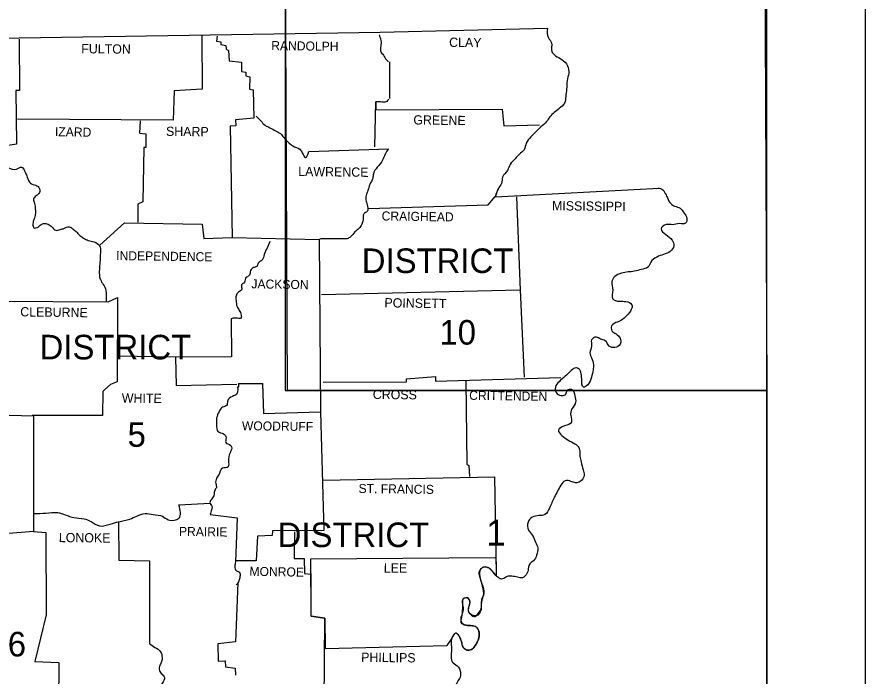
# Model space of a CAD drawing. Extents: x -492261 to -432772, y 1441225 to 1452922.
# Drawn here: x -457159 to -456748.3, y 1452098.1 to 1452417.2 of the extents above; entities that cross this region are included whole.
import ezdxf

# ---------------------------------------------------------------- set-up
doc = ezdxf.new("R2010")
doc.units = 0
for name, color, linetype in [('Default', 7, 'Continuous'), ('R_Border', 7, 'Continuous'), ('R_No Plot', 7, 'Continuous')]:
    doc.layers.add(name, color=color, linetype=linetype)

msp = doc.modelspace()

# ---------------------------------------------------------------- linework, layer by layer
at = {"layer": 'Default'}
for p, q in [((-456927.17, 1452330.17), (-456925.92, 1452334.04)), ((-456926.86, 1452331.43), (-456925.61, 1452334.46)), ((-457051.63, 1452239.76), (-457039.96, 1452239.76)), ((-457016.65, 1452154.87), (-456927.59, 1452155.5)), ((-457016.55, 1452140.93), (-457016.65, 1452154.87)), ((-457016.45, 1452126.99), (-457016.55, 1452140.93)), ((-456943.88, 1452124.9), (-456943.3, 1452128.3)), ((-457016.45, 1452126.99), (-457009.87, 1452126.05)), ((-457009.87, 1452126.05), (-457009.66, 1452111.33)), ((-457009.66, 1452111.33), (-456950.77, 1452112.79))]:
    msp.add_line(p, q, dxfattribs=at)
for points in [[(-457474.92, 1452406.92), (-457306.08, 1452406.81), (-457157.92, 1452407.12), (-456983.14, 1452409.84), (-456902.11, 1452411.72)], [(-457069.49, 1452408.06), (-457069.28, 1452382.17), (-457082.85, 1452381.44), (-457083.27, 1452367.24), (-457158.76, 1452367.66)], [(-457061.97, 1452407.96), (-457062.28, 1452405.45), (-457060.19, 1452405.14), (-457060.3, 1452403.89), (-457057.9, 1452403.37), (-457057.69, 1452401.69), (-457056.54, 1452400.96), (-457056.23, 1452395.95), (-457050.28, 1452395.33), (-457050.28, 1452390.84), (-457048.08, 1452390.52), (-457048.08, 1452388.75), (-457046.2, 1452388.23), (-457046.31, 1452382.17), (-457044.64, 1452381.86), (-457044.22, 1452368.18), (-457053.09, 1452367.34), (-457052.99, 1452364.42), (-457055.7, 1452364.32), (-457054.76, 1452310.44), (-457012.69, 1452309.5), (-457011.96, 1452225.77), (-457039.42, 1452225.03), (-457039.96, 1452239.76)], [(-457157.92, 1452406.5), (-457157.71, 1452381.65), (-457159.49, 1452381.54), (-457159.18, 1452355.55), (-457166.49, 1452354.5), (-457165.86, 1452347.51), (-457163.35, 1452344.27), (-457163.56, 1452336.02), (-457177.76, 1452335.5), (-457178.28, 1452322.76), (-457191.23, 1452322.34), (-457191.86, 1452306.89), (-457191.13, 1452305.64), (-457190.81, 1452281), (-457168.47, 1452279.54), (-457168.78, 1452224.51), (-457151.03, 1452223.99), (-457151.03, 1452168.03), (-457165.02, 1452166.98), (-457166.07, 1452154.66), (-457189.56, 1452154.56)], [(-456978.54, 1452395.43), (-456978.54, 1452377.79)], [(-456985.64, 1452354.29), (-456985.12, 1452376.11), (-456985.12, 1452372.25), (-456924.04, 1452372.56), (-456923.21, 1452364.42), (-456905.98, 1452365.05)], [(-457099.35, 1452366.93), (-457099.56, 1452360.87), (-457096.63, 1452360.66), (-457096.53, 1452353.98), (-457097.57, 1452353.98), (-457097.99, 1452327.67), (-457100.39, 1452326.62), (-457100.39, 1452317.85)], [(-457017.59, 1452352), (-456978.86, 1452353.35)], [(-456927.17, 1452330.17), (-456847.92, 1452334.25)], [(-456988.78, 1452324.43), (-456930.83, 1452326.31), (-456927.38, 1452330.28)], [(-456917.15, 1452330.07), (-456915.38, 1452284.86), (-456913.29, 1452242.78)], [(-457118.77, 1452306.68), (-457106.87, 1452317.44), (-457069.28, 1452316.91), (-457068.55, 1452309.92), (-457054.87, 1452310.44)], [(-456999.01, 1452309.71), (-457011.75, 1452309.71), (-457012.69, 1452309.5)], [(-456915.38, 1452284.86), (-457011.54, 1452282.67)], [(-457168.47, 1452279.54), (-457114.8, 1452279.22), (-457110.21, 1452281.42), (-457110.52, 1452240.59), (-457113.65, 1452239.23), (-457116.47, 1452236.83), (-457117.41, 1452235.89), (-457117.52, 1452224.2), (-457151.66, 1452224.2)], [(-457055.29, 1452270.97), (-457055.08, 1452252.6), (-457082.23, 1452252.49), (-457110.1, 1452253.02)], [(-457082.23, 1452252.49), (-457081.81, 1452238.82), (-457052.47, 1452239.34)], [(-457010.7, 1452240.38), (-456970.4, 1452240.59), (-456970.3, 1452242.05), (-456956.3, 1452243.1), (-456956.3, 1452240.9), (-456895.54, 1452242.58)], [(-457051.63, 1452239.76), (-457051.63, 1452237.98), (-457052.15, 1452237.88)], [(-456941.69, 1452240.9), (-456941.16, 1452200.71), (-456940.23, 1452200.08), (-456939.91, 1452194.65)], [(-456941.69, 1452240.9), (-456941.16, 1452200.71), (-456940.23, 1452200.08), (-456939.91, 1452194.65)], [(-456941.69, 1452240.9), (-456941.16, 1452200.71), (-456940.23, 1452200.08), (-456939.91, 1452194.65)], [(-456941.69, 1452240.9), (-456941.16, 1452200.71), (-456940.23, 1452200.08), (-456939.91, 1452194.65)], [(-456941.69, 1452240.9), (-456941.16, 1452200.71), (-456940.23, 1452200.08), (-456939.91, 1452194.65)], [(-457011.96, 1452225.77), (-457010.39, 1452168.55), (-457035.24, 1452168.44), (-457035.34, 1452166.15), (-457042.55, 1452165.73), (-457043.18, 1452153.83), (-457053.08, 1452153.83)], [(-457010.7, 1452192.88), (-456927.8, 1452194.55)], [(-456927.8, 1452194.55), (-456926.96, 1452148.82)], [(-456927.8, 1452194.55), (-456926.96, 1452148.82)], [(-456927.8, 1452194.55), (-456926.96, 1452148.82)], [(-456927.8, 1452194.55), (-456926.96, 1452148.82)], [(-456927.8, 1452194.55), (-456926.96, 1452148.82)], [(-456927.8, 1452194.55), (-456926.96, 1452148.82)], [(-456927.8, 1452194.55), (-456926.96, 1452148.82)], [(-456927.8, 1452194.55), (-456926.96, 1452148.82)], [(-457080.55, 1452180.97), (-457065.41, 1452181.7)], [(-457109.79, 1452172.83), (-457109.58, 1452154.14), (-457094.86, 1452153.83), (-457094.75, 1452113.73)], [(-457065.41, 1452176.28), (-457052.36, 1452174.6), (-457053.09, 1452153.31)], [(-457151.03, 1452168.03), (-457144.98, 1452167.61), (-457144.87, 1452127.72), (-457150.3, 1452105.07), (-457138.71, 1452104.55), (-457138.82, 1452084.59)], [(-457024.59, 1452167.92), (-457024.69, 1452154.98), (-457019.89, 1452154.98), (-457019.68, 1452147.77), (-457016.65, 1452147.46)], [(-457010.7, 1452062.36), (-457002.56, 1452062.89), (-457002.66, 1452084.08), (-457010.29, 1452084.6), (-457009.87, 1452126.05), (-457016.45, 1452126.99), (-457016.65, 1452154.87), (-456927.59, 1452155.5)], [(-456927.59, 1452155.5), (-456927.09, 1452155.51), (-456926.96, 1452148.82), (-456926.98, 1452146.78), (-456928.27, 1452148.24)], [(-456932.98, 1452138.66), (-456933.03, 1452139.03), (-456933.1, 1452139.51), (-456933.22, 1452140.12), (-456933.28, 1452140.4), (-456933.37, 1452140.79), (-456933.93, 1452143.06), (-456934.72, 1452145.65), (-456935.06, 1452147.06), (-456935.13, 1452147.61), (-456935.14, 1452147.95), (-456935.12, 1452148.26), (-456935.1, 1452148.43), (-456935.05, 1452148.64), (-456934.99, 1452148.84), (-456934.92, 1452149.04)], [(-456932.84, 1452150.84), (-456932.98, 1452150.81), (-456933.08, 1452150.78), (-456933.22, 1452150.72), (-456933.47, 1452150.61), (-456933.78, 1452150.42), (-456934.04, 1452150.21), (-456934.26, 1452150), (-456934.45, 1452149.79), (-456934.65, 1452149.52), (-456934.78, 1452149.33), (-456934.92, 1452149.04)], [(-456932.84, 1452150.84), (-456932.6, 1452150.88), (-456932.32, 1452150.9), (-456932.06, 1452150.9), (-456931.78, 1452150.87), (-456931.4, 1452150.79), (-456931.08, 1452150.69), (-456930.78, 1452150.56), (-456930.51, 1452150.4), (-456930.23, 1452150.2), (-456929.69, 1452149.7), (-456929.14, 1452149.16), (-456928.27, 1452148.24)], [(-457051.95, 1452143.28), (-457053.2, 1452114.67), (-457061.76, 1452113.73), (-457061.55, 1452105.28), (-457058.11, 1452105.38), (-457058, 1452102.46), (-457053.3, 1452101.94), (-457053.2, 1452098.49)], [(-456943.1, 1452134.4), (-456943.05, 1452135.11), (-456942.97, 1452135.36), (-456942.85, 1452135.53), (-456942.63, 1452135.71), (-456942.35, 1452135.87), (-456942.04, 1452135.98), (-456941.76, 1452136.03)], [(-456941.51, 1452136.05), (-456941.3, 1452136.04), (-456941.09, 1452135.99), (-456940.91, 1452135.91), (-456940.63, 1452135.7), (-456940.36, 1452135.47), (-456940.18, 1452135.29), (-456939.95, 1452135.01)], [(-456934.17, 1452130.23), (-456934.09, 1452131.81), (-456934.03, 1452132.68), (-456933.96, 1452133.6), (-456933.88, 1452134.77), (-456933.84, 1452135.17), (-456933.8, 1452135.39), (-456933.71, 1452135.68), (-456933.64, 1452135.85), (-456933.39, 1452136.39), (-456933.23, 1452136.72), (-456933.13, 1452136.95), (-456933.04, 1452137.18), (-456933.02, 1452137.26), (-456933, 1452137.33), (-456932.96, 1452137.45), (-456932.94, 1452137.55), (-456932.92, 1452137.71), (-456932.91, 1452137.89), (-456932.92, 1452137.96), (-456932.93, 1452138.14), (-456932.95, 1452138.34), (-456932.98, 1452138.66)], [(-456943.3, 1452128.3), (-456943.04, 1452132.03), (-456943.1, 1452134.56)], [(-456940.26, 1452130.48), (-456940.21, 1452130.87), (-456940.05, 1452131.98), (-456939.59, 1452133.93), (-456939.6, 1452134.25), (-456939.7, 1452134.58), (-456939.91, 1452134.96)], [(-456939.27, 1452127.87), (-456939.73, 1452128.4), (-456940.04, 1452128.9), (-456940.17, 1452129.23), (-456940.26, 1452129.67), (-456940.28, 1452130.11), (-456940.26, 1452130.48)], [(-456939.27, 1452127.87), (-456938.84, 1452127.51), (-456938.27, 1452127.14), (-456937.75, 1452126.93), (-456937.5, 1452126.88), (-456937.27, 1452126.86)], [(-456937.27, 1452126.86), (-456937.11, 1452126.88), (-456936.98, 1452126.92), (-456936.87, 1452126.96), (-456936.77, 1452127.02), (-456936.64, 1452127.12), (-456936.56, 1452127.21), (-456936.13, 1452127.76), (-456934.17, 1452130.23)], [(-456943.38, 1452123.42), (-456943.81, 1452123.98), (-456943.88, 1452124.9)], [(-456935.47, 1452120.37), (-456935.76, 1452120.97), (-456936.14, 1452121.46), (-456936.54, 1452121.8), (-456937.12, 1452122.09), (-456937.93, 1452122.31), (-456939.43, 1452122.56), (-456941.51, 1452122.74), (-456942.45, 1452122.93), (-456942.97, 1452123.15), (-456943.36, 1452123.41)], [(-456935.2, 1452117.03), (-456935.09, 1452117.85), (-456935.1, 1452118.72), (-456935.16, 1452119.22), (-456935.24, 1452119.59), (-456935.35, 1452120.03), (-456935.48, 1452120.39)], [(-456946.28, 1452118.83), (-456946.42, 1452118.85), (-456946.52, 1452118.84), (-456946.68, 1452118.79), (-456946.84, 1452118.71), (-456947.03, 1452118.56), (-456947.33, 1452118.25), (-456947.65, 1452117.82), (-456947.99, 1452117.3), (-456948.29, 1452116.83), (-456948.55, 1452116.28), (-456948.67, 1452115.88), (-456950.77, 1452112.79)], [(-456944.57, 1452117.02), (-456945, 1452117.63), (-456945.24, 1452117.96), (-456945.46, 1452118.22), (-456945.68, 1452118.45), (-456945.92, 1452118.65), (-456946.06, 1452118.74), (-456946.17, 1452118.8), (-456946.28, 1452118.83)], [(-456943.31, 1452113.32), (-456943.4, 1452113.71), (-456943.44, 1452113.85), (-456943.46, 1452113.94), (-456943.51, 1452114.16), (-456943.57, 1452114.36), (-456943.63, 1452114.57), (-456943.69, 1452114.72), (-456943.73, 1452114.83), (-456943.88, 1452115.32), (-456944.01, 1452115.78), (-456944.11, 1452116.05), (-456944.34, 1452116.62), (-456944.52, 1452116.94)], [(-456941.78, 1452110.96), (-456941.09, 1452110.68), (-456940.56, 1452110.58), (-456939.94, 1452110.59), (-456938.92, 1452110.9), (-456938.32, 1452111.28), (-456937.67, 1452111.91), (-456937.19, 1452112.51), (-456936.67, 1452113.45), (-456936.28, 1452114.1), (-456935.87, 1452114.99), (-456935.52, 1452115.92), (-456935.32, 1452116.54), (-456935.26, 1452116.76), (-456935.24, 1452116.86), (-456935.19, 1452117.05)], [(-457009.66, 1452111.33), (-456950.77, 1452112.79)], [(-456941.78, 1452110.96), (-456941.97, 1452111.07), (-456942.09, 1452111.15), (-456942.25, 1452111.26), (-456942.38, 1452111.38), (-456942.54, 1452111.54), (-456942.75, 1452111.82), (-456942.93, 1452112.16), (-456943.06, 1452112.47), (-456943.13, 1452112.66), (-456943.17, 1452112.8), (-456943.21, 1452112.92)]]:
    msp.add_lwpolyline(points, dxfattribs=at)
for points in [[(-456902.11, 1452411.72), (-456901.59, 1452407.12), (-456900.13, 1452404.72), (-456899.92, 1452400.34), (-456898.15, 1452398.46), (-456895.12, 1452396.58), (-456892.4, 1452393.55), (-456891.78, 1452390), (-456892.61, 1452386.35), (-456892.82, 1452382.27), (-456893.24, 1452378.72), (-456893.87, 1452375.49), (-456896.37, 1452372.88), (-456898.77, 1452371), (-456900.97, 1452368.81), (-456902.53, 1452366.51), (-456905.25, 1452364), (-456907.96, 1452361.39), (-456910.15, 1452359.1), (-456912.35, 1452356.17), (-456913.39, 1452352.94), (-456915.79, 1452350.64), (-456917.67, 1452348.55), (-456920.18, 1452345.73), (-456921.43, 1452342.91), (-456923.83, 1452339.68), (-456924.35, 1452336.54), (-456925.92, 1452334.04), (-456926.03, 1452333.62)], [(-456983.66, 1452408.48), (-456982.72, 1452405.87), (-456982.83, 1452403.05), (-456982.83, 1452400.44), (-456981.47, 1452398.67), (-456980.11, 1452396.47), (-456979.07, 1452395.53)], [(-456978.96, 1452377.47), (-456980.32, 1452376.11), (-456982.93, 1452376.11), (-456985.12, 1452376.11)], [(-457043.07, 1452369.12), (-457040.77, 1452366.72), (-457038.79, 1452364.73), (-457036.49, 1452363.59), (-457033.78, 1452362.02), (-457031.38, 1452360.77), (-457029.81, 1452358.78), (-457027.62, 1452356.59), (-457025.43, 1452354.81), (-457021.98, 1452353.14), (-457020.83, 1452351.37), (-457019.26, 1452349.18), (-457017.59, 1452352)], [(-456979.17, 1452353.25), (-456980.74, 1452350.74), (-456981.99, 1452347.82), (-456984.5, 1452344.48), (-456986.38, 1452341.24), (-456986.69, 1452339.05), (-456988.15, 1452336.13), (-456988.99, 1452333.2), (-456989.93, 1452330.7), (-456989.93, 1452328.09), (-456989.19, 1452325.48), (-456989.4, 1452323.07), (-456990.97, 1452321.93), (-456991.39, 1452318.9), (-456992.01, 1452316.81), (-456993.37, 1452314.72), (-456995.35, 1452313.16), (-456997.44, 1452310.75), (-456999.01, 1452309.71)], [(-457163.35, 1452344.27), (-457159.18, 1452343.54), (-457156.67, 1452344.48), (-457154.9, 1452341.76), (-457153.96, 1452339.68), (-457152.39, 1452336.65), (-457149.88, 1452335.71), (-457148, 1452334.04), (-457148, 1452332.26), (-457149.68, 1452330.59), (-457150.93, 1452328.92), (-457150.51, 1452326.94), (-457150.09, 1452324.22), (-457150.09, 1452321.61), (-457150.72, 1452319.21), (-457151.24, 1452317.02), (-457150.72, 1452315.14), (-457148.74, 1452315.45), (-457146.65, 1452317.02), (-457144.45, 1452317.02), (-457142.37, 1452315.87), (-457140.17, 1452313.89), (-457137.98, 1452314.3), (-457136.21, 1452314.83), (-457133.7, 1452315.56), (-457131.93, 1452314.62), (-457130.36, 1452313.36), (-457128.48, 1452311.38), (-457126.7, 1452310.13), (-457124.41, 1452308.98), (-457121.59, 1452308.25), (-457118.98, 1452306.47), (-457118.56, 1452303.45), (-457118.66, 1452300.84), (-457118.87, 1452297.6), (-457119.08, 1452294.05), (-457118.77, 1452290.6), (-457117.62, 1452288.31), (-457116.16, 1452285.59), (-457115.74, 1452283.09), (-457115.85, 1452279.12)], [(-456849.07, 1452334.14), (-456847.92, 1452334.25), (-456844.37, 1452330.49), (-456842.81, 1452327.36), (-456840.51, 1452325.58), (-456837.9, 1452324.64), (-456835.92, 1452322.24), (-456834.56, 1452319.63), (-456835.29, 1452317.33), (-456838.21, 1452317.12), (-456841.45, 1452316.6), (-456844.58, 1452316.71), (-456847.09, 1452314.62), (-456844.79, 1452311.8), (-456841.76, 1452309.19), (-456840.93, 1452306.37), (-456842.6, 1452303.65), (-456845.94, 1452302.19), (-456849.18, 1452300.94), (-456852.1, 1452298.43), (-456853.46, 1452296.03), (-456856.7, 1452294.99), (-456860.04, 1452294.05), (-456862.96, 1452293.74), (-456866.3, 1452293.11), (-456869.54, 1452291.54), (-456870.9, 1452288.83), (-456870.48, 1452284.97), (-456870.58, 1452280.89), (-456867.14, 1452279.54), (-456864.11, 1452279.43), (-456861.19, 1452277.87), (-456861.5, 1452275.57), (-456863.69, 1452272.64), (-456866.3, 1452270.35), (-456868.91, 1452269.2), (-456871.31, 1452267.01), (-456870.48, 1452264.81), (-456868.29, 1452263.35), (-456866.72, 1452260.95), (-456866.93, 1452258.76), (-456869.43, 1452257.19), (-456872.15, 1452257.82), (-456874.13, 1452260.43), (-456876.43, 1452261.26), (-456878.41, 1452262.2), (-456880.71, 1452260.85), (-456880.71, 1452257.82), (-456881.55, 1452254.58), (-456880.81, 1452252.18), (-456879.87, 1452248.84), (-456879.98, 1452246.33), (-456880.81, 1452242.78), (-456882.59, 1452239.13), (-456884.68, 1452237.98), (-456885.51, 1452241.95), (-456885.93, 1452245.19), (-456887.18, 1452247.06), (-456888.85, 1452247.17), (-456891.05, 1452245.6), (-456893.45, 1452243.2), (-456896.48, 1452240.59), (-456898.25, 1452237.98), (-456897.31, 1452234.74), (-456895.01, 1452233.91), (-456893.24, 1452234.54), (-456892.3, 1452236.62), (-456890.53, 1452236.94), (-456888.85, 1452233.7)], [(-457036.6, 1452308.56), (-457037.85, 1452305.32), (-457039.31, 1452302.19), (-457040.25, 1452299.48), (-457042.24, 1452297.91), (-457042.86, 1452296.45), (-457044.64, 1452295.82), (-457045.99, 1452293.74), (-457046.62, 1452291.86), (-457048.08, 1452291.02), (-457048.81, 1452288.72), (-457050.17, 1452287.47), (-457050.07, 1452285.38), (-457051.63, 1452283.92), (-457052.89, 1452282.25), (-457052.89, 1452279.95), (-457052.36, 1452276.93), (-457051.32, 1452275.15), (-457050.38, 1452272.85), (-457050.48, 1452271.39), (-457053.09, 1452271.39), (-457055.29, 1452270.97)], [(-457052.15, 1452237.88), (-457052.68, 1452234.43), (-457054.66, 1452233.49), (-457056.96, 1452231.19), (-457057.48, 1452229.11), (-457059.36, 1452228.27), (-457061.13, 1452226.08), (-457062.28, 1452223.05), (-457062.28, 1452219.92), (-457061.55, 1452216.37), (-457058.94, 1452215.43), (-457057.69, 1452213.34), (-457057.9, 1452211.15), (-457055.39, 1452209.69), (-457054.97, 1452208.43), (-457055.39, 1452207.08), (-457056.54, 1452203.21), (-457056.44, 1452200.6), (-457056.64, 1452199.45), (-457059.46, 1452198.72), (-457061.13, 1452195.9), (-457062.28, 1452193.92), (-457062.7, 1452191.31), (-457062.39, 1452189.43), (-457063.22, 1452187.97), (-457063.54, 1452185.78), (-457064.58, 1452183.9), (-457065.52, 1452182.12), (-457064.48, 1452180.03), (-457064.79, 1452178.57), (-457065.41, 1452176.28)], [(-456888.85, 1452233.7), (-456888.44, 1452230.67), (-456890.21, 1452227.44), (-456890.84, 1452224.2), (-456890.53, 1452220.96), (-456893.87, 1452219.19), (-456896.79, 1452217.1), (-456895.12, 1452214.59), (-456891.99, 1452212.3), (-456888.85, 1452210.52), (-456886.87, 1452208.75), (-456886.35, 1452204.47), (-456885.83, 1452201.75), (-456884.78, 1452197.99), (-456884.36, 1452195.38), (-456886.24, 1452192.25), (-456888.44, 1452191.62), (-456890.73, 1452192.35), (-456893.45, 1452192.56), (-456895.64, 1452190.47), (-456897.21, 1452187.55), (-456898.77, 1452184.63), (-456899.92, 1452182.12), (-456901.07, 1452179.41), (-456903.37, 1452176.28), (-456906.19, 1452175.75), (-456909.53, 1452174.92), (-456911.51, 1452172.62), (-456911.2, 1452168.76), (-456909.32, 1452166.15), (-456907.86, 1452162.91), (-456906.81, 1452160.09), (-456907.34, 1452156.54), (-456908.8, 1452153.93), (-456910.68, 1452152.37), (-456911.51, 1452149.02), (-456912.87, 1452146.52), (-456914.12, 1452145.68), (-456916.63, 1452145.89), (-456919.34, 1452146.41), (-456921.64, 1452146.21), (-456923.83, 1452145.06), (-456926.03, 1452145.79), (-456928.32, 1452148.29), (-456930.2, 1452150.17), (-456932.29, 1452150.9), (-456934.48, 1452149.76), (-456934.9, 1452146.31), (-456933.86, 1452142.76), (-456932.92, 1452137.96), (-456933.86, 1452135.03), (-456934.17, 1452130.23)], [(-457150.82, 1452176.8), (-457144.98, 1452177.01), (-457139.23, 1452177.21), (-457135.58, 1452176.17), (-457131.4, 1452174.81), (-457126.5, 1452174.19), (-457123.05, 1452172.83), (-457118.98, 1452170.74), (-457113.76, 1452171.68), (-457109.69, 1452172.73), (-457104.36, 1452174.08), (-457100.91, 1452175.54), (-457096.95, 1452176.8), (-457092.98, 1452176.28), (-457088.49, 1452175.44), (-457085.67, 1452173.77), (-457080.55, 1452174.5), (-457080.55, 1452180.97)], [(-457053.09, 1452153.31), (-457053.51, 1452151.22), (-457052.68, 1452149.02), (-457051.21, 1452148.29), (-457051.01, 1452146.21), (-457051.53, 1452144.12), (-457051.95, 1452143.28), (-457052.89, 1452142.03)], [(-456934.17, 1452130.23), (-456936.57, 1452127.2), (-456940.12, 1452129.08), (-456940.12, 1452131.59), (-456939.6, 1452134.2), (-456940.85, 1452135.87), (-456943.04, 1452135.14), (-456943.04, 1452131.9), (-456943.25, 1452128.77), (-456943.88, 1452124.28), (-456942.42, 1452122.92), (-456939.08, 1452122.5), (-456936.68, 1452121.88), (-456935.21, 1452119.48), (-456935.32, 1452116.55), (-456936.47, 1452113.73), (-456938.14, 1452111.44), (-456940.75, 1452110.6), (-456942.84, 1452111.96), (-456943.67, 1452114.67), (-456944.61, 1452117.08), (-456946.39, 1452118.85), (-456948.26, 1452116.87), (-456948.68, 1452113.21), (-456948.58, 1452110.08), (-456948.58, 1452105.8), (-456948.19, 1452105.02), (-456945.86, 1452102.98), (-456944.19, 1452099.74), (-456944.71, 1452096.82), (-456945.25, 1452095.96), (-456946.7, 1452093.37), (-456947.53, 1452090.35), (-456948.37, 1452086.27), (-456948.26, 1452081.78), (-456949, 1452077.4), (-456950.46, 1452074.48), (-456953.17, 1452072.07), (-456954.95, 1452070.51), (-456956.41, 1452068.94), (-456957.14, 1452065.81), (-456957.66, 1452063.62), (-456959.65, 1452061.01), (-456961.21, 1452060.8), (-456962.46, 1452061.84), (-456962.88, 1452063.62), (-456962.88, 1452065.39), (-456963.72, 1452067.17), (-456966.33, 1452067.9), (-456968.42, 1452067.79), (-456969.36, 1452066.33), (-456968, 1452062.26), (-456967.48, 1452059.65), (-456968.09, 1452056.96), (-456968.13, 1452056.73), (-456968.21, 1452056.1), (-456967.79, 1452055.68), (-456971.55, 1452053.7), (-456974.58, 1452053.39), (-456977.08, 1452052.65), (-456979.48, 1452051.09), (-456980.63, 1452048.79), (-456982.3, 1452046.91), (-456983.76, 1452045.14), (-456985.75, 1452044.3), (-456987.94, 1452044.72), (-456990.86, 1452045.03), (-456992.54, 1452042.94), (-456992.01, 1452039.92), (-456990.03, 1452038.14), (-456987.11, 1452037.31), (-456984.08, 1452037.52), (-456981.15, 1452037.83), (-456978.44, 1452036.37), (-456978.96, 1452033.55), (-456981.57, 1452032.19), (-456985.44, 1452031.77), (-456988.57, 1452032.09), (-456992.33, 1452031.25), (-456994.21, 1452028.85), (-456993.16, 1452025.19), (-456989.09, 1452023.73), (-456987.21, 1452020.29), (-456987.11, 1452017.05), (-456988.46, 1452012.77), (-456990.34, 1452010.79), (-456994, 1452009.95), (-456996.82, 1452009.43), (-456997.23, 1452004.63), (-456998.49, 1452002.22), (-457000.68, 1452001.49), (-457003.81, 1452003.06), (-457005.69, 1452003.79), (-457007.99, 1452004.84), (-457010.91, 1452006.61), (-457013.1, 1452006.3), (-457012.48, 1452001.7), (-457012.27, 1452001.49), (-457009.76, 1451998.05), (-457007.26, 1451995.33), (-457006.11, 1451992.1)], [(-457094.75, 1452113.73), (-457092.14, 1452111.96), (-457089.43, 1452109.87), (-457088.7, 1452107.05), (-457088.91, 1452105.07), (-457089.74, 1452103.4), (-457089.95, 1452100.79), (-457088.7, 1452098.91), (-457087.55, 1452097.34), (-457088.7, 1452094.52), (-457090.68, 1452091.91), (-457091.73, 1452088.99), (-457092.46, 1452084.6)]]:
    msp.add_spline(points, degree=3, dxfattribs=at)
at = {"layer": 'R_Border'}
msp.add_line((-456795.84, 1450553.05), (-456795.84, 1452607.65), dxfattribs=at)
at = {"layer": 'R_No Plot'}
for points in [[(-460081.71, 1452646.6), (-456748.31, 1452646.6), (-456748.31, 1450513.22), (-460081.71, 1450513.22)], [(-457618.44, 1452607.65), (-457618.44, 1452508.85), (-457261.12, 1452508.85), (-457261.12, 1452479.65), (-457029.12, 1452479.65), (-457029.12, 1452236.32), (-456795.84, 1452236.32), (-456795.84, 1450553.05), (-459957.64, 1450553.05), (-459957.64, 1452607.65)], [(-457029.12, 1452479.65), (-456797.05, 1452479.65), (-456795.84, 1452236.32), (-457027.92, 1452236.32)]]:
    msp.add_lwpolyline(points, close=True, dxfattribs=at)

# ---------------------------------------------------------------- texts
at = {"layer": 'Default'}
for s, height, rotation, p in [('CLAY', 4.489, 359.2258, (-456949.73, 1452402.74)), ('FULTON', 4.489, 359.4996, (-457127.85, 1452399.61)), ('RANDOLPH', 4.386, 359.2584, (-457035.87, 1452401.17)), ('GREENE', 4.49, 359.2361, (-456967.06, 1452365.15)), ('IZARD', 4.385, 358.9259, (-457140.59, 1452359.51)), ('SHARP', 4.489, 359.3905, (-457086.82, 1452359.62)), ('LAWRENCE', 4.49, 359.2678, (-457022.81, 1452340.2)), ('MISSISSIPPI', 4.4891, 359.3097, (-456899.92, 1452323.6)), ('CRAIGHEAD', 4.386, 359.1159, (-456982.41, 1452318.69)), ('INDEPENDENCE', 4.3845, 359.2188, (-457110.94, 1452299.48)), ('JACKSON', 4.384, 359.1352, (-457045.47, 1452285.8)), ('POINSETT', 4.489, 359.1987, (-456981.05, 1452276.61)), ('CLEBURNE', 4.489, 359.2535, (-457157.4, 1452272.23)), ('WHITE', 4.49, 359.3139, (-457108.22, 1452230.46)), ('CROSS', 4.489, 359.384, (-456986.69, 1452232.24)), ('CRITTENDEN', 4.386, 359.213, (-456940.02, 1452231.82)), ('WOODRUFF', 4.384, 359.2748, (-457050.07, 1452217.1)), ('ST. FRANCIS', 4.3845, 359.2216, (-456993.58, 1452186.72)), ('PRAIRIE', 4.386, 359.2116, (-457080.55, 1452165.94)), ('LONOKE', 4.49, 359.4974, (-457138.71, 1452162.91)), ('LEE', 4.49, 359.4327, (-456981.36, 1452148.19)), ('MONROE', 4.384, 359.0331, (-457046.41, 1452146.62)), ('PHILLIPS', 4.489, 359.318, (-456992.33, 1452104.96))]:
    msp.add_text(s, height=height, rotation=rotation, dxfattribs=at).set_placement(p)
for s, height, p in [('DISTRICT', 11.903, (-456992.01, 1452293.21)), ('10', 11.903, (-456954.4, 1452258.55)), ('DISTRICT', 11.903, (-457147.99, 1452251.39)), ('5', 11.9, (-457105.4, 1452209.06)), ('1', 12.53, (-456931.66, 1452161.24)), ('DISTRICT', 11.903, (-457032.73, 1452160.51)), ('DISTRICT 6', 11.903, (-457241.24, 1452107.57))]:
    msp.add_text(s, height=height, dxfattribs=at).set_placement(p)

doc.saveas('drawing.dxf')
